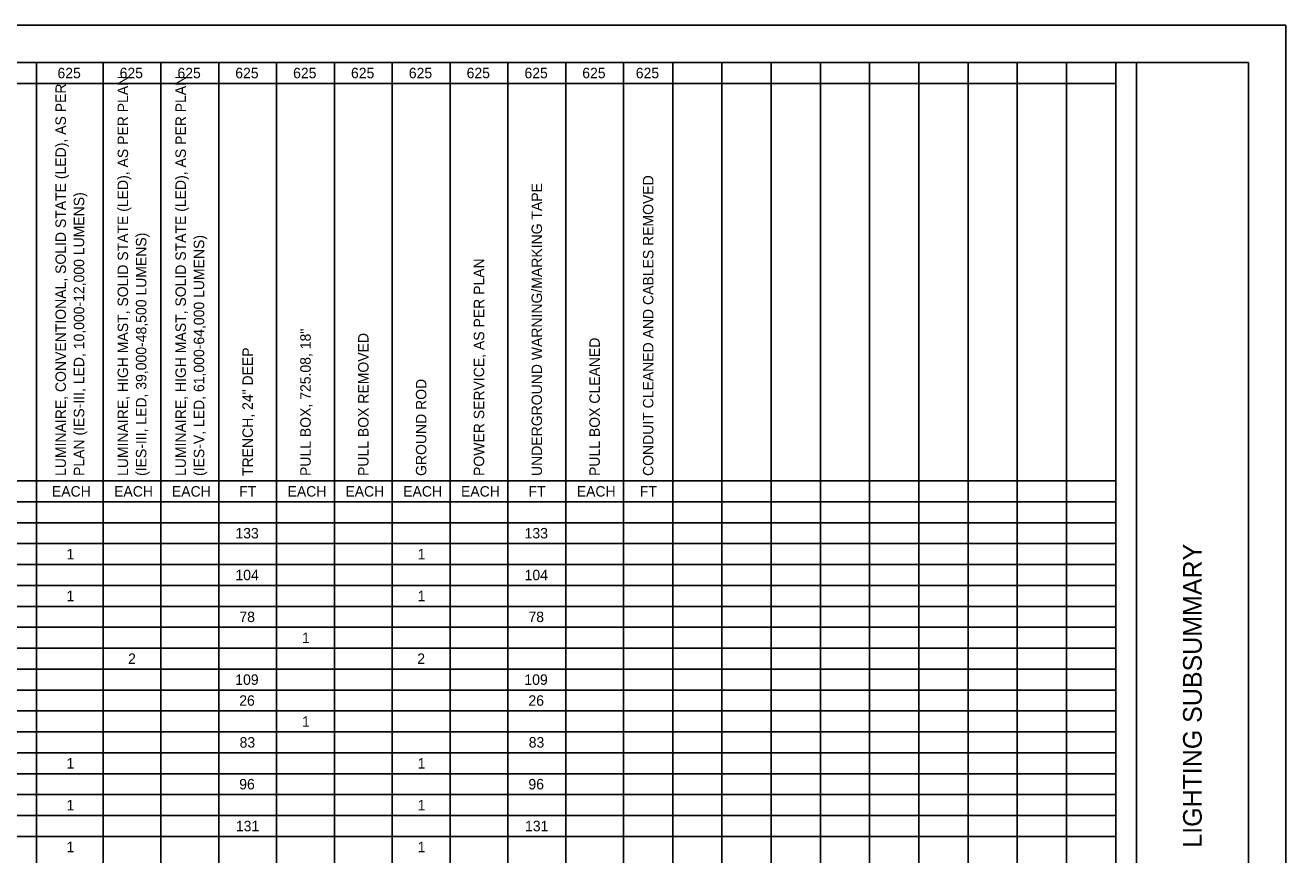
# Model space of a CAD drawing. Extents: x 0 to 34, y 0 to 22.
# Drawn here: x 17.13 to 34, y 10.89 to 22 of the extents above; entities that cross this region are included whole.
import ezdxf

# ---------------------------------------------------------------- set-up
doc = ezdxf.new("R2010")
doc.units = 0
for name, color, linetype in [('SH_Border', 7, 'Continuous'), ('SH_Cut_Line', 7, 'Continuous'), ('SH_Data', 7, 'Continuous'), ('SH_Text', 7, 'Continuous')]:
    doc.layers.add(name, color=color, linetype=linetype)

msp = doc.modelspace()

# ---------------------------------------------------------------- linework, layer by layer
at = {"layer": 'SH_Border'}
msp.add_line((32, 0.5), (32, 21.5), dxfattribs=at)
msp.add_lwpolyline([(1.5, 21.5), (33.5, 21.5), (33.5, 0.5), (1.5, 0.5)], close=True, dxfattribs=at)
at = {"layer": 'SH_Cut_Line'}
msp.add_lwpolyline([(0, 0), (34, 0), (34, 22), (0, 22)], close=True, dxfattribs=at)
at = {"layer": 'SH_Text'}
for p, q in [((1.5, 21.5), (31.724, 21.5)), ((17.279, 21.5), (17.279, 0.5)), ((18.168, 21.5), (18.168, 0.5)), ((18.942, 21.5), (18.942, 0.5)), ((19.716, 21.5), (19.716, 0.5)), ((20.491, 21.5), (20.491, 0.5)), ((21.265, 21.5), (21.265, 0.5)), ((22.039, 21.5), (22.039, 0.5)), ((22.813, 21.5), (22.813, 0.5)), ((23.587, 21.5), (23.587, 0.5)), ((24.361, 21.5), (24.361, 0.5)), ((25.135, 21.5), (25.135, 0.5)), ((25.794, 21.5), (25.794, 0.5)), ((26.453, 21.5), (26.453, 0.5)), ((27.112, 21.5), (27.112, 0.5)), ((27.771, 21.5), (27.771, 0.5)), ((28.429, 21.5), (28.429, 0.5)), ((29.088, 21.5), (29.088, 0.5)), ((29.747, 21.5), (29.747, 0.5)), ((30.406, 21.5), (30.406, 0.5)), ((31.065, 21.5), (31.065, 0.5)), ((31.724, 21.5), (31.724, 0.5)), ((8.451, 21.22), (31.724, 21.22)), ((8.451, 15.9), (31.724, 15.9)), ((1.5, 15.62), (31.724, 15.62)), ((1.5, 15.34), (31.724, 15.34)), ((1.5, 15.06), (31.724, 15.06)), ((1.5, 14.78), (31.724, 14.78)), ((1.5, 14.5), (31.724, 14.5)), ((1.5, 14.22), (31.724, 14.22)), ((1.5, 13.94), (31.724, 13.94)), ((1.5, 13.66), (31.724, 13.66)), ((1.5, 13.38), (31.724, 13.38)), ((1.5, 13.1), (31.724, 13.1)), ((1.5, 12.82), (31.724, 12.82)), ((1.5, 12.54), (31.724, 12.54)), ((1.5, 12.26), (31.724, 12.26)), ((1.5, 11.98), (31.724, 11.98)), ((1.5, 11.7), (31.724, 11.7)), ((1.5, 11.42), (31.724, 11.42)), ((1.5, 11.14), (31.724, 11.14))]:
    msp.add_line(p, q, dxfattribs=at)

# ---------------------------------------------------------------- texts
at = {"layer": 'SH_Data'}
msp.add_text('LIGHTING SUBSUMMARY', height=0.25, rotation=90, dxfattribs=at).set_placement((32.875, 10.99))
at = {"layer": 'SH_Text'}
for s, p in [('625', (17.558, 21.29)), ('625', (18.39, 21.29)), ('625', (19.164, 21.29)), ('625', (19.938, 21.29)), ('625', (20.712, 21.29)), ('625', (21.487, 21.29)), ('625', (22.261, 21.29)), ('625', (23.035, 21.29)), ('625', (23.809, 21.29)), ('625', (24.583, 21.29)), ('625', (25.299, 21.29)), ('EACH', (17.484, 15.69)), ('EACH', (18.316, 15.69)), ('EACH', (19.09, 15.69)), ('FT', (19.991, 15.69)), ('EACH', (20.638, 15.69)), ('EACH', (21.412, 15.69)), ('EACH', (22.186, 15.69)), ('EACH', (22.96, 15.69)), ('FT', (23.862, 15.69)), ('EACH', (24.509, 15.69)), ('FT', (25.353, 15.69)), ('133', (19.94, 15.13)), ('133', (23.811, 15.13)), ('1', (17.678, 14.85)), ('1', (22.38, 14.85)), ('104', (19.94, 14.57)), ('104', (23.811, 14.57)), ('1', (17.678, 14.29)), ('1', (22.38, 14.29)), ('78', (19.993, 14.01)), ('78', (23.863, 14.01)), ('1', (20.832, 13.73)), ('2', (18.503, 13.45)), ('2', (22.374, 13.45)), ('109', (19.938, 13.17)), ('109', (23.808, 13.17)), ('26', (19.991, 12.89)), ('26', (23.862, 12.89)), ('1', (20.832, 12.61)), ('83', (19.996, 12.33)), ('83', (23.866, 12.33)), ('1', (17.678, 12.05)), ('1', (22.38, 12.05)), ('96', (19.991, 11.77)), ('96', (23.862, 11.77)), ('1', (17.678, 11.49)), ('1', (22.38, 11.49)), ('131', (19.946, 11.21)), ('131', (23.817, 11.21)), ('1', (17.678, 10.93)), ('1', (22.38, 10.93))]:
    msp.add_text(s, height=0.14, dxfattribs=at).set_placement(p)
for s, p in [('LUMINAIRE, HIGH MAST, SOLID STATE (LED), AS PER PLAN ', (18.503, 15.966)), ('LUMINAIRE, HIGH MAST, SOLID STATE (LED), AS PER PLAN ', (19.277, 15.966)), ('LUMINAIRE, CONVENTIONAL, SOLID STATE (LED), AS PER ', (17.671, 15.966)), ('CONDUIT CLEANED AND CABLES REMOVED', (25.535, 15.966)), ('PLAN (IES-III, LED, 10,000-12,000 LUMENS)', (17.916, 15.966)), ('UNDERGROUND WARNING/MARKING TAPE', (24.044, 15.966)), ('(IES-III, LED, 39,000-48,500 LUMENS)', (18.748, 15.966)), ('(IES-V, LED, 61,000-64,000 LUMENS)', (19.522, 15.966)), ('POWER SERVICE, AS PER PLAN', (23.27, 15.966)), ('PULL BOX, 725.08, 18"', (20.948, 15.966)), ('PULL BOX REMOVED', (21.722, 15.966)), ('PULL BOX CLEANED', (24.818, 15.966)), ('TRENCH, 24" DEEP', (20.174, 15.966)), ('GROUND ROD', (22.496, 15.966))]:
    msp.add_text(s, height=0.14, rotation=90, dxfattribs=at).set_placement(p)

doc.saveas('drawing.dxf')
